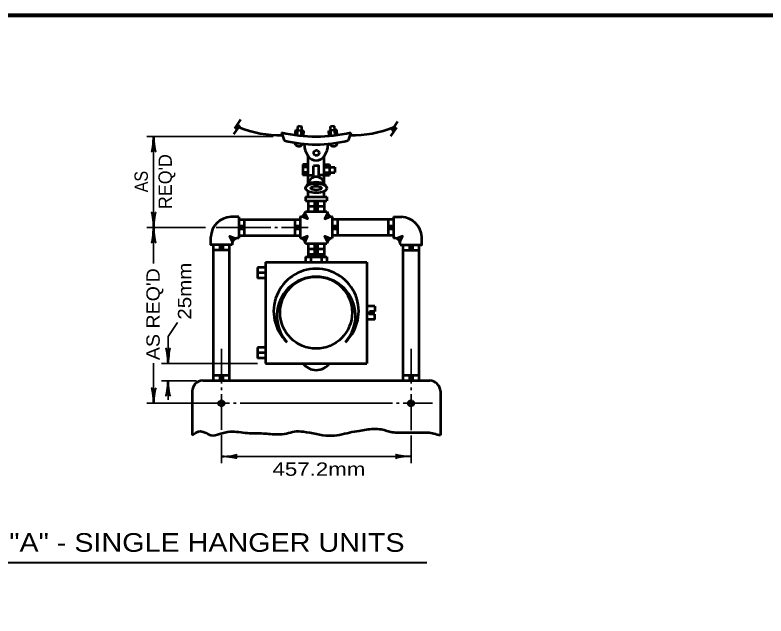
# Model space of a CAD drawing. Extents: x -35 to 821, y -10 to 534.
# Drawn here: x 188.7 to 357.6, y 392 to 527.4 of the extents above; entities that cross this region are included whole.
import ezdxf
from ezdxf.enums import TextEntityAlignment as Align

# ---------------------------------------------------------------- set-up
doc = ezdxf.new("R2010")
doc.units = 0
doc.header["$LTSCALE"] = 1.2
doc.layers.add('1', color=7, linetype='Continuous', lineweight=35)

msp = doc.modelspace()

# ---------------------------------------------------------------- linework, layer by layer
at = {"layer": '1', "lineweight": 53}
for p, q in [((238.136, 501.83), (239.513, 503.796)), ((237.954, 500.511), (239.33, 502.477)), ((238.136, 501.83), (239.33, 502.477)), ((252.199, 500.296), (252.382, 502.388)), ((252.382, 502.388), (253.253, 502.219)), ((253.106, 500.124), (253.253, 502.219)), ((260.548, 502.353), (259.645, 502.216)), ((259.791, 500.121), (259.645, 502.216)), ((260.695, 500.259), (260.548, 502.353)), ((274.548, 502.028), (273.171, 500.062)), ((274.731, 503.347), (273.354, 501.381)), ((274.548, 502.028), (273.354, 501.381)), ((248.647, 500.882), (249.247, 499.082)), ((251.748, 500.306), (251.856, 501.531)), ((251.856, 501.531), (253.639, 501.289)), ((253.556, 500.105), (253.639, 501.289)), ((261.06, 501.487), (259.259, 501.287)), ((259.341, 500.105), (259.259, 501.287)), ((261.143, 500.306), (261.06, 501.487)), ((264.247, 500.882), (263.647, 499.082)), ((254.62, 489.239), (254.62, 495.611)), ((258.274, 489.239), (258.274, 495.611)), ((254.62, 493.682), (253.42, 493.682)), ((253.42, 493.682), (253.42, 491.282)), ((255.82, 491.282), (255.82, 493.382)), ((258.274, 493.682), (259.474, 493.682)), ((259.474, 493.682), (259.474, 491.282)), ((254.62, 493.082), (253.42, 493.082)), ((254.62, 491.882), (253.42, 491.882)), ((258.274, 493.082), (260.674, 493.082)), ((258.274, 491.882), (260.674, 491.882)), ((260.674, 493.082), (260.674, 491.882)), ((254.62, 491.282), (253.42, 491.282)), ((254.62, 491.282), (255.82, 491.282)), ((258.274, 491.282), (257.074, 491.282)), ((258.274, 491.282), (259.474, 491.282)), ((254.62, 486.413), (254.62, 487.682)), ((258.274, 486.413), (258.274, 487.682)), ((254.02, 486.413), (258.874, 486.413)), ((254.02, 486.413), (254.02, 485.513)), ((254.02, 485.513), (258.874, 485.513)), ((254.62, 485.513), (254.62, 483.113)), ((255.82, 484.913), (257.074, 484.913)), ((258.274, 485.513), (258.274, 483.113)), ((258.874, 486.413), (258.874, 485.513)), ((254.62, 484.313), (258.274, 484.313)), ((255.82, 483.713), (257.074, 483.713)), ((239.02, 481.913), (237.221, 481.913)), ((239.02, 481.913), (239.02, 477.113)), ((252.821, 481.921), (252.821, 477.113)), ((254.02, 483.113), (258.874, 483.113)), ((260.078, 481.921), (260.078, 477.106)), ((273.878, 481.913), (273.878, 477.113)), ((273.878, 481.913), (275.678, 481.913)), ((239.02, 481.313), (252.821, 481.313)), ((239.621, 480.113), (239.621, 478.913)), ((240.221, 481.313), (240.221, 477.713)), ((251.621, 481.313), (251.621, 477.713)), ((252.221, 480.113), (252.221, 478.913)), ((273.878, 481.313), (260.078, 481.313)), ((260.678, 480.113), (260.678, 478.913)), ((261.278, 481.313), (261.278, 477.713)), ((272.678, 481.313), (272.678, 477.713)), ((273.278, 480.113), (273.278, 478.913)), ((239.02, 477.713), (252.821, 477.713)), ((273.878, 477.713), (260.078, 477.713)), ((233.321, 445.013), (233.321, 475.613)), ((235.721, 475.013), (234.52, 475.013)), ((236.921, 445.013), (236.921, 475.613)), ((254.029, 475.913), (258.87, 475.913)), ((254.629, 475.913), (254.629, 472.913)), ((255.829, 475.313), (257.07, 475.313)), ((258.27, 475.913), (258.27, 472.913)), ((275.978, 445.013), (275.978, 475.613)), ((277.178, 475.013), (278.378, 475.013)), ((279.578, 445.013), (279.578, 475.613)), ((236.921, 474.413), (233.321, 474.413)), ((254.629, 474.713), (258.27, 474.713)), ((254.629, 473.513), (258.27, 473.513)), ((255.829, 474.113), (257.07, 474.113)), ((275.978, 474.413), (279.578, 474.413)), ((245.029, 471.713), (267.87, 471.713)), ((245.029, 471.713), (245.029, 448.913)), ((254.029, 472.913), (258.87, 472.913)), ((254.029, 472.913), (254.029, 471.713)), ((255.229, 472.913), (255.229, 471.713)), ((255.829, 472.949), (257.07, 472.949)), ((257.67, 472.913), (257.67, 471.713)), ((258.87, 472.913), (258.87, 471.713)), ((267.87, 471.713), (267.87, 448.913)), ((245.029, 470.513), (243.229, 470.513)), ((243.229, 470.513), (243.229, 468.113)), ((245.029, 469.313), (243.229, 469.313)), ((245.029, 468.113), (243.229, 468.113)), ((269.67, 461.813), (267.87, 461.813)), ((269.67, 461.813), (269.67, 460.613)), ((269.67, 460.613), (268.47, 460.613)), ((269.67, 458.813), (269.67, 460.013)), ((269.67, 458.813), (267.87, 458.813)), ((245.029, 452.513), (243.229, 452.513)), ((243.229, 452.513), (243.229, 450.113)), ((245.029, 451.313), (243.229, 451.313)), ((245.029, 450.113), (243.229, 450.113)), ((245.029, 448.913), (267.87, 448.913)), ((236.921, 446.213), (233.321, 446.213)), ((279.578, 446.213), (275.978, 446.213)), ((281.978, 445.013), (230.921, 445.013)), ((235.721, 445.613), (234.52, 445.613)), ((278.378, 445.613), (277.178, 445.613)), ((228.52, 442.613), (228.52, 432.713)), ((284.383, 442.613), (284.383, 432.713))]:
    msp.add_line(p, q, dxfattribs=at)
at = {"layer": '1'}
for p, q in [((246.773, 500.009), (218.371, 500.009)), ((219.882, 479.513), (219.882, 500.009)), ((231.571, 479.513), (218.371, 479.513)), ((219.882, 479.513), (219.882, 471.381)), ((246.221, 479.513), (233.971, 479.513)), ((242.621, 479.513), (242.02, 479.513)), ((247.721, 479.513), (247.121, 479.513)), ((254.621, 479.513), (248.621, 479.513)), ((223.125, 454.921), (225.216, 458.125)), ((223.125, 448.913), (223.125, 454.921)), ((235.121, 452.213), (235.121, 444.387)), ((277.783, 452.213), (277.783, 444.387)), ((219.882, 448.937), (219.882, 439.913)), ((243.229, 448.913), (221.649, 448.913)), ((229.549, 445.007), (221.649, 445.007)), ((223.125, 445.013), (223.125, 440.7)), ((235.121, 443.487), (235.121, 442.887)), ((277.783, 443.487), (277.783, 442.887)), ((235.121, 441.987), (235.121, 433.913)), ((277.783, 441.987), (277.783, 433.847)), ((218.371, 439.913), (236.923, 439.913)), ((237.839, 439.913), (238.439, 439.913)), ((239.339, 439.913), (273.58, 439.913)), ((274.48, 439.913), (275.08, 439.913)), ((275.983, 439.913), (282.583, 439.913)), ((235.121, 432.714), (235.121, 426.413)), ((277.783, 432.647), (277.783, 426.413)), ((235.121, 427.944), (277.783, 427.944))]:
    msp.add_line(p, q, dxfattribs=at)
at = {"layer": '1', "lineweight": 40}
msp.add_line((111.055, 404.049), (281.348, 404.049), dxfattribs=at)
at = {"layer": '1', "lineweight": 158}
msp.add_lwpolyline([(814.384, 527.35), (22.684, 527.25), (22.784, 1.25)], dxfattribs=at)
at = {"layer": '1', "lineweight": 53}
for points in [[(257.074, 491.282), (257.074, 493.382), (255.82, 493.382)], [(253.924, 482.73), (254.506, 481.474), (253.197, 482.011)], [(258.97, 482.73), (258.388, 481.474), (259.698, 482.011)], [(237.52, 475.613), (232.721, 475.613), (232.721, 477.413)], [(237.609, 476.312), (237.027, 477.568), (238.337, 477.031)], [(253.932, 476.303), (254.514, 477.559), (253.205, 477.022)], [(258.966, 476.296), (258.384, 477.552), (259.694, 477.015)], [(275.29, 476.312), (275.871, 477.568), (274.562, 477.031)], [(275.378, 475.613), (280.178, 475.613), (280.178, 477.413)], [(269.67, 460.013), (268.47, 460.013), (268.47, 460.613)]]:
    msp.add_lwpolyline(points, dxfattribs=at)
for centre, radius in [((256.501, 496.29), 0.6), ((256.437, 460.327), 8.1), ((235.123, 439.914), 0.6), ((277.783, 439.915), 0.6)]:
    msp.add_circle(centre, radius, dxfattribs=at)
for centre, radius, start, end in [((248.068, 524.024), 23.724, 247.65241, 271.85853), ((264.827, 524.024), 23.724, 268.14138, 292.34759), ((256.447, 534.232), 34.25, 256.83593, 283.1638), ((256.447, 527.432), 29.25, 255.74997, 284.25003), ((252.561, 498.797), 0.986, 192.33045, 332.21364), ((260.337, 498.798), 0.986, 207.78636, 347.66955), ((256.447, 489.079), 1.834, 4.98578, 175.01422), ((237.573, 477.06), 4.866, 94.15966, 175.84035), ((252.702, 483.239), 1.324, 275.11437, 291.91656), ((252.702, 483.239), 1.324, 291.91656, 354.5292), ((252.702, 483.239), 1.324, 291.91738, 337.37313), ((260.192, 483.239), 1.324, 185.4708, 248.08344), ((260.192, 483.239), 1.324, 202.62687, 248.08262), ((260.192, 483.239), 1.324, 248.08344, 265.0377), ((275.325, 477.06), 4.866, 4.15965, 85.84034), ((238.831, 475.803), 1.324, 111.91656, 188.24718), ((238.831, 475.803), 1.324, 111.91738, 157.37313), ((238.831, 475.803), 1.324, 81.75282, 111.91656), ((252.71, 475.794), 1.324, 68.08344, 85.22882), ((252.71, 475.794), 1.324, 5.16652, 68.08344), ((252.71, 475.794), 1.324, 22.62687, 68.08262), ((260.188, 475.787), 1.324, 111.91656, 174.5292), ((260.188, 475.787), 1.324, 111.91738, 157.37313), ((260.188, 475.787), 1.324, 94.77118, 111.91656), ((274.068, 475.803), 1.324, 68.08344, 98.24718), ((274.068, 475.803), 1.324, 351.75282, 68.08344), ((274.068, 475.803), 1.324, 22.62687, 68.08262), ((256.449, 460.643), 9.57, 313.60282, 226.39718), ((256.449, 459.59), 8.837, 318.31863, 221.68137), ((256.449, 451.204), 3.791, 217.18292, 322.81708), ((231.047, 442.487), 2.53, 92.86473, 177.13527), ((281.851, 442.487), 2.53, 2.86473, 87.13527)]:
    msp.add_arc(centre, radius, start, end, dxfattribs=at)
at = {"layer": '1', "lineweight": 40}
for centre, major_axis, ratio, start_param, end_param in [((219.628, 498.665), (0.211, 2.108), 0.07063, 3.1407148, 5.41811), ((219.628, 498.665), (0.211, 2.108), 0.07063, 3.1407148, 5.41811), ((220.214, 498.7), (-0.187, 2.143), 0.122415, 0.8963533, 3.1415927), ((220.214, 498.7), (-0.187, 2.143), 0.122415, 0.8963533, 3.1415927), ((219.551, 480.823), (0.187, -2.143), 0.122415, 0.8963533, 3.1415927), ((219.551, 480.823), (0.187, -2.143), 0.122415, 0.8963533, 3.1415927), ((220.136, 480.858), (-0.211, -2.108), 0.07063, 3.1407148, 5.41811), ((220.136, 480.858), (-0.211, -2.108), 0.07063, 3.1407148, 5.41811), ((219.628, 478.168), (0.211, 2.108), 0.07063, 3.1407148, 5.41811), ((219.628, 478.168), (0.211, 2.108), 0.07063, 3.1407148, 5.41811), ((220.214, 478.204), (-0.187, 2.143), 0.122415, 0.8963533, 3.1415927), ((220.214, 478.204), (-0.187, 2.143), 0.122415, 0.8963533, 3.1415927), ((222.794, 450.223), (0.187, -2.143), 0.122415, 0.8963533, 3.1415927), ((223.379, 450.258), (-0.211, -2.108), 0.07063, 3.1407148, 5.41811), ((222.871, 443.668), (0.211, 2.108), 0.07063, 3.1407148, 5.41811), ((223.457, 443.704), (-0.187, 2.143), 0.122415, 0.8963533, 3.1415927), ((219.551, 441.223), (0.187, -2.143), 0.122415, 0.8963533, 3.1415927), ((219.551, 441.223), (0.187, -2.143), 0.122415, 0.8963533, 3.1415927), ((220.136, 441.258), (-0.211, -2.108), 0.07063, 3.1407148, 5.41811), ((220.136, 441.258), (-0.211, -2.108), 0.07063, 3.1407148, 5.41811), ((236.576, 427.69), (-2.108, 0.211), 0.07063, 3.1407148, 5.41811), ((236.541, 428.275), (-2.143, -0.187), 0.122415, 0.8963533, 3.1415927), ((276.462, 427.622), (2.143, 0.187), 0.122415, 0.8963533, 3.1415927), ((276.427, 428.207), (2.108, -0.211), 0.07063, 3.1407148, 5.41811)]:
    msp.add_ellipse(centre, major_axis=major_axis, ratio=ratio, start_param=start_param, end_param=end_param, dxfattribs=at)
at = {"layer": '1', "lineweight": 53}
for centre, major_axis, ratio, start_param, end_param in [((256.447, 498.482), (0, 3.9), 0.692308, 1.615522, 4.6676498), ((256.447, 488.363), (2.4, 0), 0.5625, 6.2831853, 9.424778)]:
    msp.add_ellipse(centre, major_axis=major_axis, ratio=ratio, start_param=start_param, end_param=end_param, dxfattribs=at)
for major_axis, ratio in [((2.4, 0), 0.4375), ((1.2, 0), 0.375)]:
    msp.add_ellipse((256.447, 488.363), major_axis=major_axis, ratio=ratio, dxfattribs=at)
msp.add_spline([(228.52, 432.713), (230.436, 433.652), (232.78, 432.735), (234.717, 433.041), (237.061, 433.55), (240.934, 433.245), (244.501, 433.143), (247.763, 432.939), (249.801, 433.143), (251.534, 433.55), (253.572, 433.55), (259.382, 432.633), (261.726, 432.837), (263.968, 433.346), (266.108, 433.754), (269.37, 434.162), (271.102, 434.06), (273.548, 433.448), (274.975, 433.346), (277.32, 433.346), (279.562, 433.346), (281.498, 433.346), (284.383, 432.713)], degree=3, dxfattribs=at)

# ---------------------------------------------------------------- texts
at = {"layer": '1'}
msp.add_text("REQ'D", height=3, rotation=90, dxfattribs=at).set_placement((223.973, 489.839), align=Align.CENTER)
at = {"layer": '1', "width": 0.9}
msp.add_text('AS', height=3, rotation=90, dxfattribs=at).set_placement((218.573, 489.839), align=Align.CENTER)
at = {"layer": '1'}
for s, width, p in [("AS REQ'D", 1.1, (221.246, 449.631)), ('25mm', 1.15, (228.339, 458.757))]:
    msp.add_text(s, height=3, rotation=90, dxfattribs=dict(at, width=width)).set_placement(p)
for s, height, width, p in [('457.2mm', 3, 1.25, (246.604, 423.592)), ('SUSPENSION METHOD "A" - SINGLE HANGER UNITS', 4.2, 1.15, (113.481, 406.476))]:
    msp.add_text(s, height=height, dxfattribs=dict(at, width=width)).set_placement(p)

doc.saveas('drawing.dxf')
